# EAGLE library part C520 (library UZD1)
A/D-Wandler 3-stellig -99mV..999mV HOLD-EingangBetriebsart 0..0.4 VUmsetzung 4 Sa/s 0,8..1,6 VMesswert halten 3,2..5,5 VUmsetzung 100 Sa/s Standard-Beschaltung: NP: 13 k&Omega; fest + 10 k&Omega; Poti nach + 13 k&Omega; fest IC: 330 nF nach Masse (hochwertiger Kondensator!) EW: 22 k&Omega; Poti nach Masse Ausgänge sind allesamt Offene Kollektoren; ggf. Pull-Ups nicht vergessen! Zulässige Gleichtakteingangsspannung an IH und IL: ± 15 V
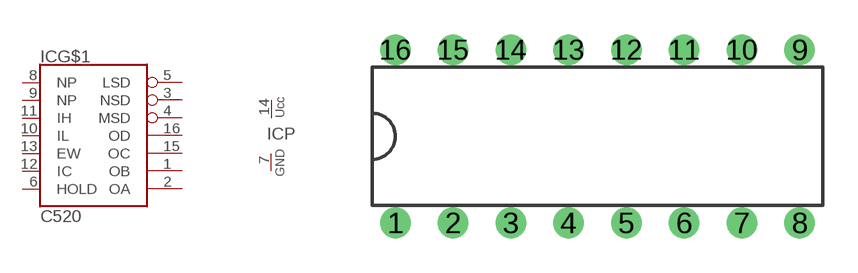
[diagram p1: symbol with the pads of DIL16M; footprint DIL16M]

Designator prefix IC; gates G$1=C520 P=PWRN

## C520D  [DIL16M]
1  G$1:OB  oc
2  G$1:OA  oc
3  G$1:NSD  oc
4  G$1:MSD  oc
5  G$1:LSD  oc
6  G$1:HOLD  in
7  P:GND  pwr
8  G$1:NP  in
9  G$1:NP  in
10  G$1:IL  in
11  G$1:IH  in
12  G$1:IC  in
13  G$1:EW  in
14  P:5P  pwr
15  G$1:OC  oc
16  G$1:OD  oc

## Footprint DIL16M (pad centres in mm)
DIL-Gehäuse e=2,5, w=7,5 (metrisch)
drill 0.813 round: 1 -8.75,-3.75; 2 -6.25,-3.75; 3 -3.75,-3.75; 4 -1.25,-3.75; 5 1.25,-3.75; 6 3.75,-3.75; 7 6.25,-3.75; 8 8.75,-3.75; 9 8.75,3.75; 10 6.25,3.75; 11 3.75,3.75; 12 1.25,3.75; 13 -1.25,3.75; 14 -3.75,3.75; 15 -6.25,3.75; 16 -8.75,3.75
